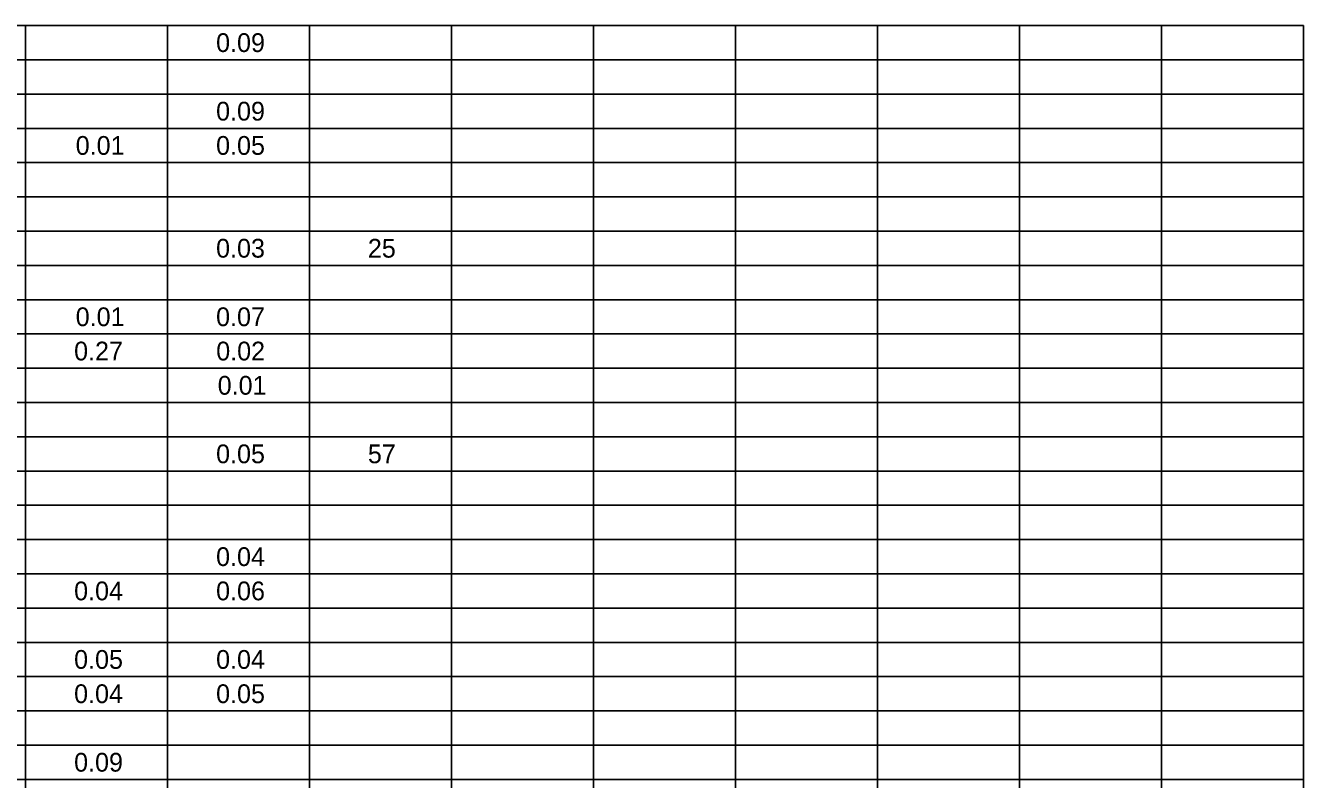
# Model space of a CAD drawing. Extents: x 0 to 34, y 0 to 22.
# Drawn here: x 14.06 to 24.5, y 10.02 to 16.18 of the extents above; entities that cross this region are included whole.
import ezdxf

# ---------------------------------------------------------------- set-up
doc = ezdxf.new("R2010")
doc.units = 0
doc.layers.add('SH_Text', color=7, linetype='Continuous')

msp = doc.modelspace()

# ---------------------------------------------------------------- linework, layer by layer
at = {"layer": 'SH_Text'}
for p, q in [((3.02, 16.18), (14.06, 16.18)), ((14.06, 16.18), (16.38, 16.18)), ((14.06, 16.18), (14.06, 15.9)), ((15.22, 16.18), (15.22, 15.9)), ((16.38, 16.18), (21.02, 16.18)), ((16.38, 16.18), (16.38, 15.9)), ((17.54, 16.18), (17.54, 15.9)), ((18.7, 16.18), (18.7, 15.9)), ((19.86, 16.18), (19.86, 15.9)), ((21.02, 16.18), (23.34, 16.18)), ((21.02, 16.18), (21.02, 15.9)), ((22.18, 16.18), (22.18, 15.9)), ((23.34, 16.18), (24.5, 16.18)), ((23.34, 16.18), (23.34, 15.9)), ((24.5, 16.18), (24.5, 15.9)), ((3.02, 15.9), (14.06, 15.9)), ((14.06, 15.9), (16.38, 15.9)), ((14.06, 15.9), (14.06, 15.62)), ((15.22, 15.9), (15.22, 15.62)), ((16.38, 15.9), (21.02, 15.9)), ((16.38, 15.9), (16.38, 15.62)), ((17.54, 15.9), (17.54, 15.62)), ((18.7, 15.9), (18.7, 15.62)), ((19.86, 15.9), (19.86, 15.62)), ((21.02, 15.9), (23.34, 15.9)), ((21.02, 15.9), (21.02, 15.62)), ((22.18, 15.9), (22.18, 15.62)), ((23.34, 15.9), (24.5, 15.9)), ((23.34, 15.9), (23.34, 15.62)), ((24.5, 15.9), (24.5, 15.62)), ((3.02, 15.62), (14.06, 15.62)), ((14.06, 15.62), (16.38, 15.62)), ((14.06, 15.62), (14.06, 15.34)), ((15.22, 15.62), (15.22, 15.34)), ((16.38, 15.62), (21.02, 15.62)), ((16.38, 15.62), (16.38, 15.34)), ((17.54, 15.62), (17.54, 15.34)), ((18.7, 15.62), (18.7, 15.34)), ((19.86, 15.62), (19.86, 15.34)), ((21.02, 15.62), (23.34, 15.62)), ((21.02, 15.62), (21.02, 15.34)), ((22.18, 15.62), (22.18, 15.34)), ((23.34, 15.62), (24.5, 15.62)), ((23.34, 15.62), (23.34, 15.34)), ((24.5, 15.62), (24.5, 15.34)), ((3.02, 15.34), (14.06, 15.34)), ((14.06, 15.34), (16.38, 15.34)), ((14.06, 15.34), (14.06, 15.06)), ((15.22, 15.34), (15.22, 15.06)), ((16.38, 15.34), (21.02, 15.34)), ((16.38, 15.34), (16.38, 15.06)), ((17.54, 15.34), (17.54, 15.06)), ((18.7, 15.34), (18.7, 15.06)), ((19.86, 15.34), (19.86, 15.06)), ((21.02, 15.34), (23.34, 15.34)), ((21.02, 15.34), (21.02, 15.06)), ((22.18, 15.34), (22.18, 15.06)), ((23.34, 15.34), (24.5, 15.34)), ((23.34, 15.34), (23.34, 15.06)), ((24.5, 15.34), (24.5, 15.06)), ((3.02, 15.06), (14.06, 15.06)), ((14.06, 15.06), (16.38, 15.06)), ((14.06, 15.06), (14.06, 14.78)), ((15.22, 15.06), (15.22, 14.78)), ((16.38, 15.06), (21.02, 15.06)), ((16.38, 15.06), (16.38, 14.78)), ((17.54, 15.06), (17.54, 14.78)), ((18.7, 15.06), (18.7, 14.78)), ((19.86, 15.06), (19.86, 14.78)), ((21.02, 15.06), (23.34, 15.06)), ((21.02, 15.06), (21.02, 14.78)), ((22.18, 15.06), (22.18, 14.78)), ((23.34, 15.06), (24.5, 15.06)), ((23.34, 15.06), (23.34, 14.78)), ((24.5, 15.06), (24.5, 14.78)), ((3.02, 14.78), (14.06, 14.78)), ((14.06, 14.78), (16.38, 14.78)), ((14.06, 14.78), (14.06, 14.5)), ((15.22, 14.78), (15.22, 14.5)), ((16.38, 14.78), (21.02, 14.78)), ((16.38, 14.78), (16.38, 14.5)), ((17.54, 14.78), (17.54, 14.5)), ((18.7, 14.78), (18.7, 14.5)), ((19.86, 14.78), (19.86, 14.5)), ((21.02, 14.78), (23.34, 14.78)), ((21.02, 14.78), (21.02, 14.5)), ((22.18, 14.78), (22.18, 14.5)), ((23.34, 14.78), (24.5, 14.78)), ((23.34, 14.78), (23.34, 14.5)), ((24.5, 14.78), (24.5, 14.5)), ((3.02, 14.5), (14.06, 14.5)), ((14.06, 14.5), (16.38, 14.5)), ((14.06, 14.5), (14.06, 14.22)), ((15.22, 14.5), (15.22, 14.22)), ((16.38, 14.5), (21.02, 14.5)), ((16.38, 14.5), (16.38, 14.22)), ((17.54, 14.5), (17.54, 14.22)), ((18.7, 14.5), (18.7, 14.22)), ((19.86, 14.5), (19.86, 14.22)), ((21.02, 14.5), (23.34, 14.5)), ((21.02, 14.5), (21.02, 14.22)), ((22.18, 14.5), (22.18, 14.22)), ((23.34, 14.5), (24.5, 14.5)), ((23.34, 14.5), (23.34, 14.22)), ((24.5, 14.5), (24.5, 14.22)), ((3.02, 14.22), (14.06, 14.22)), ((14.06, 14.22), (16.38, 14.22)), ((14.06, 14.22), (14.06, 13.94)), ((15.22, 14.22), (15.22, 13.94)), ((16.38, 14.22), (21.02, 14.22)), ((16.38, 14.22), (16.38, 13.94)), ((17.54, 14.22), (17.54, 13.94)), ((18.7, 14.22), (18.7, 13.94)), ((19.86, 14.22), (19.86, 13.94)), ((21.02, 14.22), (23.34, 14.22)), ((21.02, 14.22), (21.02, 13.94)), ((22.18, 14.22), (22.18, 13.94)), ((23.34, 14.22), (24.5, 14.22)), ((23.34, 14.22), (23.34, 13.94)), ((24.5, 14.22), (24.5, 13.94)), ((3.02, 13.94), (14.06, 13.94)), ((14.06, 13.94), (16.38, 13.94)), ((14.06, 13.94), (14.06, 13.66)), ((15.22, 13.94), (15.22, 13.66)), ((16.38, 13.94), (21.02, 13.94)), ((16.38, 13.94), (16.38, 13.66)), ((17.54, 13.94), (17.54, 13.66)), ((18.7, 13.94), (18.7, 13.66)), ((19.86, 13.94), (19.86, 13.66)), ((21.02, 13.94), (23.34, 13.94)), ((21.02, 13.94), (21.02, 13.66)), ((22.18, 13.94), (22.18, 13.66)), ((23.34, 13.94), (24.5, 13.94)), ((23.34, 13.94), (23.34, 13.66)), ((24.5, 13.94), (24.5, 13.66)), ((3.02, 13.66), (14.06, 13.66)), ((14.06, 13.66), (16.38, 13.66)), ((14.06, 13.66), (14.06, 13.38)), ((15.22, 13.66), (15.22, 13.38)), ((16.38, 13.66), (21.02, 13.66)), ((16.38, 13.66), (16.38, 13.38)), ((17.54, 13.66), (17.54, 13.38)), ((18.7, 13.66), (18.7, 13.38)), ((19.86, 13.66), (19.86, 13.38)), ((21.02, 13.66), (23.34, 13.66)), ((21.02, 13.66), (21.02, 13.38)), ((22.18, 13.66), (22.18, 13.38)), ((23.34, 13.66), (24.5, 13.66)), ((23.34, 13.66), (23.34, 13.38)), ((24.5, 13.66), (24.5, 13.38)), ((3.02, 13.38), (14.06, 13.38)), ((14.06, 13.38), (16.38, 13.38)), ((14.06, 13.38), (14.06, 13.1)), ((15.22, 13.38), (15.22, 13.1)), ((16.38, 13.38), (21.02, 13.38)), ((16.38, 13.38), (16.38, 13.1)), ((17.54, 13.38), (17.54, 13.1)), ((18.7, 13.38), (18.7, 13.1)), ((19.86, 13.38), (19.86, 13.1)), ((21.02, 13.38), (23.34, 13.38)), ((21.02, 13.38), (21.02, 13.1)), ((22.18, 13.38), (22.18, 13.1)), ((23.34, 13.38), (24.5, 13.38)), ((23.34, 13.38), (23.34, 13.1)), ((24.5, 13.38), (24.5, 13.1)), ((3.02, 13.1), (14.06, 13.1)), ((14.06, 13.1), (16.38, 13.1)), ((14.06, 13.1), (14.06, 12.82)), ((15.22, 13.1), (15.22, 12.82)), ((16.38, 13.1), (21.02, 13.1)), ((16.38, 13.1), (16.38, 12.82)), ((17.54, 13.1), (17.54, 12.82)), ((18.7, 13.1), (18.7, 12.82)), ((19.86, 13.1), (19.86, 12.82)), ((21.02, 13.1), (23.34, 13.1)), ((21.02, 13.1), (21.02, 12.82)), ((22.18, 13.1), (22.18, 12.82)), ((23.34, 13.1), (24.5, 13.1)), ((23.34, 13.1), (23.34, 12.82)), ((24.5, 13.1), (24.5, 12.82)), ((3.02, 12.82), (14.06, 12.82)), ((14.06, 12.82), (16.38, 12.82)), ((14.06, 12.82), (14.06, 12.54)), ((15.22, 12.82), (15.22, 12.54)), ((16.38, 12.82), (21.02, 12.82)), ((16.38, 12.82), (16.38, 12.54)), ((17.54, 12.82), (17.54, 12.54)), ((18.7, 12.82), (18.7, 12.54)), ((19.86, 12.82), (19.86, 12.54)), ((21.02, 12.82), (23.34, 12.82)), ((21.02, 12.82), (21.02, 12.54)), ((22.18, 12.82), (22.18, 12.54)), ((23.34, 12.82), (24.5, 12.82)), ((23.34, 12.82), (23.34, 12.54)), ((24.5, 12.82), (24.5, 12.54)), ((3.02, 12.54), (14.06, 12.54)), ((14.06, 12.54), (16.38, 12.54)), ((14.06, 12.54), (14.06, 12.26)), ((15.22, 12.54), (15.22, 12.26)), ((16.38, 12.54), (21.02, 12.54)), ((16.38, 12.54), (16.38, 12.26)), ((17.54, 12.54), (17.54, 12.26)), ((18.7, 12.54), (18.7, 12.26)), ((19.86, 12.54), (19.86, 12.26)), ((21.02, 12.54), (23.34, 12.54)), ((21.02, 12.54), (21.02, 12.26)), ((22.18, 12.54), (22.18, 12.26)), ((23.34, 12.54), (24.5, 12.54)), ((23.34, 12.54), (23.34, 12.26)), ((24.5, 12.54), (24.5, 12.26)), ((3.02, 12.26), (14.06, 12.26)), ((14.06, 12.26), (16.38, 12.26)), ((14.06, 12.26), (14.06, 11.98)), ((15.22, 12.26), (15.22, 11.98)), ((16.38, 12.26), (21.02, 12.26)), ((16.38, 12.26), (16.38, 11.98)), ((17.54, 12.26), (17.54, 11.98)), ((18.7, 12.26), (18.7, 11.98)), ((19.86, 12.26), (19.86, 11.98)), ((21.02, 12.26), (23.34, 12.26)), ((21.02, 12.26), (21.02, 11.98)), ((22.18, 12.26), (22.18, 11.98)), ((23.34, 12.26), (24.5, 12.26)), ((23.34, 12.26), (23.34, 11.98)), ((24.5, 12.26), (24.5, 11.98)), ((3.02, 11.98), (14.06, 11.98)), ((14.06, 11.98), (16.38, 11.98)), ((14.06, 11.98), (14.06, 11.7)), ((15.22, 11.98), (15.22, 11.7)), ((16.38, 11.98), (21.02, 11.98)), ((16.38, 11.98), (16.38, 11.7)), ((17.54, 11.98), (17.54, 11.7)), ((18.7, 11.98), (18.7, 11.7)), ((19.86, 11.98), (19.86, 11.7)), ((21.02, 11.98), (23.34, 11.98)), ((21.02, 11.98), (21.02, 11.7)), ((22.18, 11.98), (22.18, 11.7)), ((23.34, 11.98), (24.5, 11.98)), ((23.34, 11.98), (23.34, 11.7)), ((24.5, 11.98), (24.5, 11.7)), ((3.02, 11.7), (14.06, 11.7)), ((14.06, 11.7), (16.38, 11.7)), ((14.06, 11.7), (14.06, 11.42)), ((15.22, 11.7), (15.22, 11.42)), ((16.38, 11.7), (21.02, 11.7)), ((16.38, 11.7), (16.38, 11.42)), ((17.54, 11.7), (17.54, 11.42)), ((18.7, 11.7), (18.7, 11.42)), ((19.86, 11.7), (19.86, 11.42)), ((21.02, 11.7), (23.34, 11.7)), ((21.02, 11.7), (21.02, 11.42)), ((22.18, 11.7), (22.18, 11.42)), ((23.34, 11.7), (24.5, 11.7)), ((23.34, 11.7), (23.34, 11.42)), ((24.5, 11.7), (24.5, 11.42)), ((3.02, 11.42), (14.06, 11.42)), ((14.06, 11.42), (16.38, 11.42)), ((14.06, 11.42), (14.06, 11.14)), ((15.22, 11.42), (15.22, 11.14)), ((16.38, 11.42), (21.02, 11.42)), ((16.38, 11.42), (16.38, 11.14)), ((17.54, 11.42), (17.54, 11.14)), ((18.7, 11.42), (18.7, 11.14)), ((19.86, 11.42), (19.86, 11.14)), ((21.02, 11.42), (23.34, 11.42)), ((21.02, 11.42), (21.02, 11.14)), ((22.18, 11.42), (22.18, 11.14)), ((23.34, 11.42), (24.5, 11.42)), ((23.34, 11.42), (23.34, 11.14)), ((24.5, 11.42), (24.5, 11.14)), ((3.02, 11.14), (14.06, 11.14)), ((14.06, 11.14), (16.38, 11.14)), ((14.06, 11.14), (14.06, 10.86)), ((15.22, 11.14), (15.22, 10.86)), ((16.38, 11.14), (21.02, 11.14)), ((16.38, 11.14), (16.38, 10.86)), ((17.54, 11.14), (17.54, 10.86)), ((18.7, 11.14), (18.7, 10.86)), ((19.86, 11.14), (19.86, 10.86)), ((21.02, 11.14), (23.34, 11.14)), ((21.02, 11.14), (21.02, 10.86)), ((22.18, 11.14), (22.18, 10.86)), ((23.34, 11.14), (24.5, 11.14)), ((23.34, 11.14), (23.34, 10.86)), ((24.5, 11.14), (24.5, 10.86)), ((3.02, 10.86), (14.06, 10.86)), ((14.06, 10.86), (16.38, 10.86)), ((14.06, 10.86), (14.06, 10.58)), ((15.22, 10.86), (15.22, 10.58)), ((16.38, 10.86), (21.02, 10.86)), ((16.38, 10.86), (16.38, 10.58)), ((17.54, 10.86), (17.54, 10.58)), ((18.7, 10.86), (18.7, 10.58)), ((19.86, 10.86), (19.86, 10.58)), ((21.02, 10.86), (23.34, 10.86)), ((21.02, 10.86), (21.02, 10.58)), ((22.18, 10.86), (22.18, 10.58)), ((23.34, 10.86), (24.5, 10.86)), ((23.34, 10.86), (23.34, 10.58)), ((24.5, 10.86), (24.5, 10.58)), ((3.02, 10.58), (14.06, 10.58)), ((14.06, 10.58), (16.38, 10.58)), ((14.06, 10.58), (14.06, 10.3)), ((15.22, 10.58), (15.22, 10.3)), ((16.38, 10.58), (21.02, 10.58)), ((16.38, 10.58), (16.38, 10.3)), ((17.54, 10.58), (17.54, 10.3)), ((18.7, 10.58), (18.7, 10.3)), ((19.86, 10.58), (19.86, 10.3)), ((21.02, 10.58), (23.34, 10.58)), ((21.02, 10.58), (21.02, 10.3)), ((22.18, 10.58), (22.18, 10.3)), ((23.34, 10.58), (24.5, 10.58)), ((23.34, 10.58), (23.34, 10.3)), ((24.5, 10.58), (24.5, 10.3)), ((3.02, 10.3), (14.06, 10.3)), ((14.06, 10.3), (16.38, 10.3)), ((14.06, 10.3), (14.06, 10.02)), ((15.22, 10.3), (15.22, 10.02)), ((16.38, 10.3), (21.02, 10.3)), ((16.38, 10.3), (16.38, 10.02)), ((17.54, 10.3), (17.54, 10.02)), ((18.7, 10.3), (18.7, 10.02)), ((19.86, 10.3), (19.86, 10.02)), ((21.02, 10.3), (23.34, 10.3)), ((21.02, 10.3), (21.02, 10.02)), ((22.18, 10.3), (22.18, 10.02)), ((23.34, 10.3), (24.5, 10.3)), ((23.34, 10.3), (23.34, 10.02)), ((24.5, 10.3), (24.5, 10.02)), ((3.02, 10.02), (14.06, 10.02)), ((14.06, 10.02), (16.38, 10.02)), ((14.06, 10.02), (14.06, 9.74)), ((15.22, 10.02), (15.22, 9.74)), ((16.38, 10.02), (21.02, 10.02)), ((16.38, 10.02), (16.38, 9.74)), ((17.54, 10.02), (17.54, 9.74)), ((18.7, 10.02), (18.7, 9.74)), ((19.86, 10.02), (19.86, 9.74)), ((21.02, 10.02), (23.34, 10.02)), ((21.02, 10.02), (21.02, 9.74)), ((22.18, 10.02), (22.18, 9.74)), ((23.34, 10.02), (24.5, 10.02)), ((23.34, 10.02), (23.34, 9.74)), ((24.5, 10.02), (24.5, 9.74))]:
    msp.add_line(p, q, dxfattribs=at)

# ---------------------------------------------------------------- texts
for s, p in [('0.09', (15.617, 15.964)), ('0.09', (15.617, 15.404)), ('0.01', (14.47, 15.124)), ('0.05', (15.617, 15.124)), ('0.03', (15.617, 14.284)), ('25', (16.857, 14.284)), ('0.01', (14.47, 13.724)), ('0.07', (15.617, 13.724)), ('0.27', (14.457, 13.444)), ('0.02', (15.618, 13.444)), ('0.01', (15.63, 13.164)), ('0.05', (15.617, 12.604)), ('57', (16.857, 12.604)), ('0.04', (15.617, 11.764)), ('0.04', (14.457, 11.484)), ('0.06', (15.617, 11.484)), ('0.05', (14.457, 10.924)), ('0.04', (15.617, 10.924)), ('0.04', (14.457, 10.644)), ('0.05', (15.617, 10.644)), ('0.09', (14.457, 10.084))]:
    msp.add_text(s, height=0.1533, dxfattribs=at).set_placement(p)

doc.saveas('drawing.dxf')
